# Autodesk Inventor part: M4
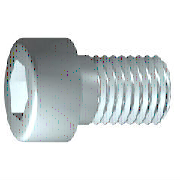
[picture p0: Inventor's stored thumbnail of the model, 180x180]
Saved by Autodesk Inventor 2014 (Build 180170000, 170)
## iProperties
IsCustomPart: 0
Company: 한국ATC센터
Created: 2014-10
Part Number: M4
Material: 강철
Description: 6각머리 태핑 나사
Document SubType Name: Modeling
Standard: KS B 1003
Designer: KYOUNG IL JANG
Standards Organization: KS
Language: ko-KR
Size Designation: M 4 x 10
Categories: <MemberInstance><Categories><Category DisplayName="조임쇠" InternalName="e4da775c-781d-43d5-af7c-5136215cf5a6" Mnemonic="FSTN"><Category DisplayName="볼트" InternalN
Density: 7.85 g/cm^3
Mass: 2.03451 g
Surface Area: 3.0572 cm^2
Volume: 0.259174 cm^3
Appearance: Black Cast
Author: KYOUNG IL JANG
Revision Number: 1
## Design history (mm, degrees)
sketch "스케치1"
  geometry: L1 (-1, 0)-(10, 0); L2 (10, 0)-(10, 2); L3 (10, 2)-(1.75, 2); L4 (1.75, 2)-(1.32, 2); L5 (1.32, 2)-(0, 2); L6 (0, 2)-(0, 3.5); L7 (0, 3.5)-(-4, 3.5); L8 (-4, 3.5)-(-4, 1.732); L9 (-4, 1.732)-(-2, 1.732); L10 (-2, 1.732)-(-1, 0); L11 (-6.8, 0)-(12.8, 0) reference; L12 (0, -0.7)-(0, 4.2) reference; L13 (1.75, 2)-(0, 2)
  constraints: 22 end point, 6 parallel, 2 collinear, 2 perpendicular, 1 horizontal, 1 point on line
  dimensions: "d1" = 8.25 distance from line of L3.end L2 (= GEL); "d2" = 0.42952 distance of L4.end L3.end (computed from GAL); "d3" = 4 distance between parallel lines of L8 L6 (= KOH); "d4" = 2 distance of L8.end L9.end (= INTI); "d5" = 60 deg angle of L10 L1; "d6" = 4 diameter of L3 L1 (= GD); "d7" = 4 diameter of L5 L1 (= BDM); "d8" = 3.4641 diameter of L9 L1 (= 1.1547 x SW); "d9" = 7 diameter of L7 L1 (= KOD); "d26" = 10 distance between parallel lines of L12 L2 (= NLG)
revolve "본체" sketch "스케치1" stored, may be unused: angle "d10" = 90 deg
sketch "스케치2"
  geometry: L1 (0, -4.9)-(0, 4.9) reference; L2 (-4.9, 0)-(4.9, 0) reference; L3 (1.732, 0)-(0.866, -1.5); L4 (0.866, -1.5)-(-0.866, -1.5); L5 (-0.866, -1.5)-(-1.732, 0); L6 (-1.732, 0)-(-0.866, 1.5); L7 (-0.866, 1.5)-(0.866, 1.5); L8 (0.866, 1.5)-(1.732, 0); 2 further points
  constraints: 12 end point, 1 coincident, 1 horizontal alignment, 1 point on line, 12 other
extrude "슬롯" join sketch "스케치2" stored distance "d11" = 10; taper "d12" = 0 deg
workplane "Work Plane1"
fillet "Fillet2" dims "d30" = 0.1 (= R)
body "Solid1"
fillet "모깎기1" dims "d17" = 0.4 (= RR)
feature "스레드" dims "d13" = 8.25 (= GEL), "d14" = 0
chamfer "모따기1" distance "d15" = 0.42941 (= -0.5 x SPD + 0.5 x GD); stored, may be unused: second distance "d16" = 0.42941 (= GUL), angle "d27" = 45 deg
other parameters: "GD" = 4 (= NND) [user parameter; used in 2 equation terms], "NLG" = 10 [user parameter; used in 1 equation term], "GEL" = 8.25 [user parameter; used in 2 equation terms], "KOD" = 7 [user parameter; used in 1 equation term], "KOH" = 4 [user parameter; used in 1 equation term], "INTI" = 2 [user parameter; used in 1 equation term], "GAL" = 0.42941 (= 0.61345 x PTC) [user parameter; used in 1 equation term], "GUL" = 0.42941 (= 0.61345 x PTC) [user parameter; used in 1 equation term], "BDM" = 4 (= NND) [user parameter; used in 1 equation term], "SW" = 3 [user parameter; used in 2 equation terms], "RR" = 0.4 [user parameter; used in 1 equation term], "SPD" = 3.14117 (= NND - 1.2269 x PTC) [user parameter; used in 1 equation term], "d19" = 0, "d28" = 0, "d29" = 0, "R" = 0.1 [user parameter; used in 1 equation term], "PHH" = 0.2 [user parameter], "GD1" = 3.14117 (= THREADDIA - 1.2269 x PTC) [user parameter], "THREADDIA" = 4 [user parameter; used in 1 equation term], "FAWI" = 45 deg [user parameter], "TPU" = 14.28571 (computed from PTC) [user parameter], "PTC" = 0.7 [user parameter; used in 5 equation terms], "NND" = 4 [user parameter; used in 3 equation terms], "TOA" = 30 deg [user parameter], "E0" = 3.465 (= 1.155 x SW) [user parameter]
